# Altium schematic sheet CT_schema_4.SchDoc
size 300 x 247 mm
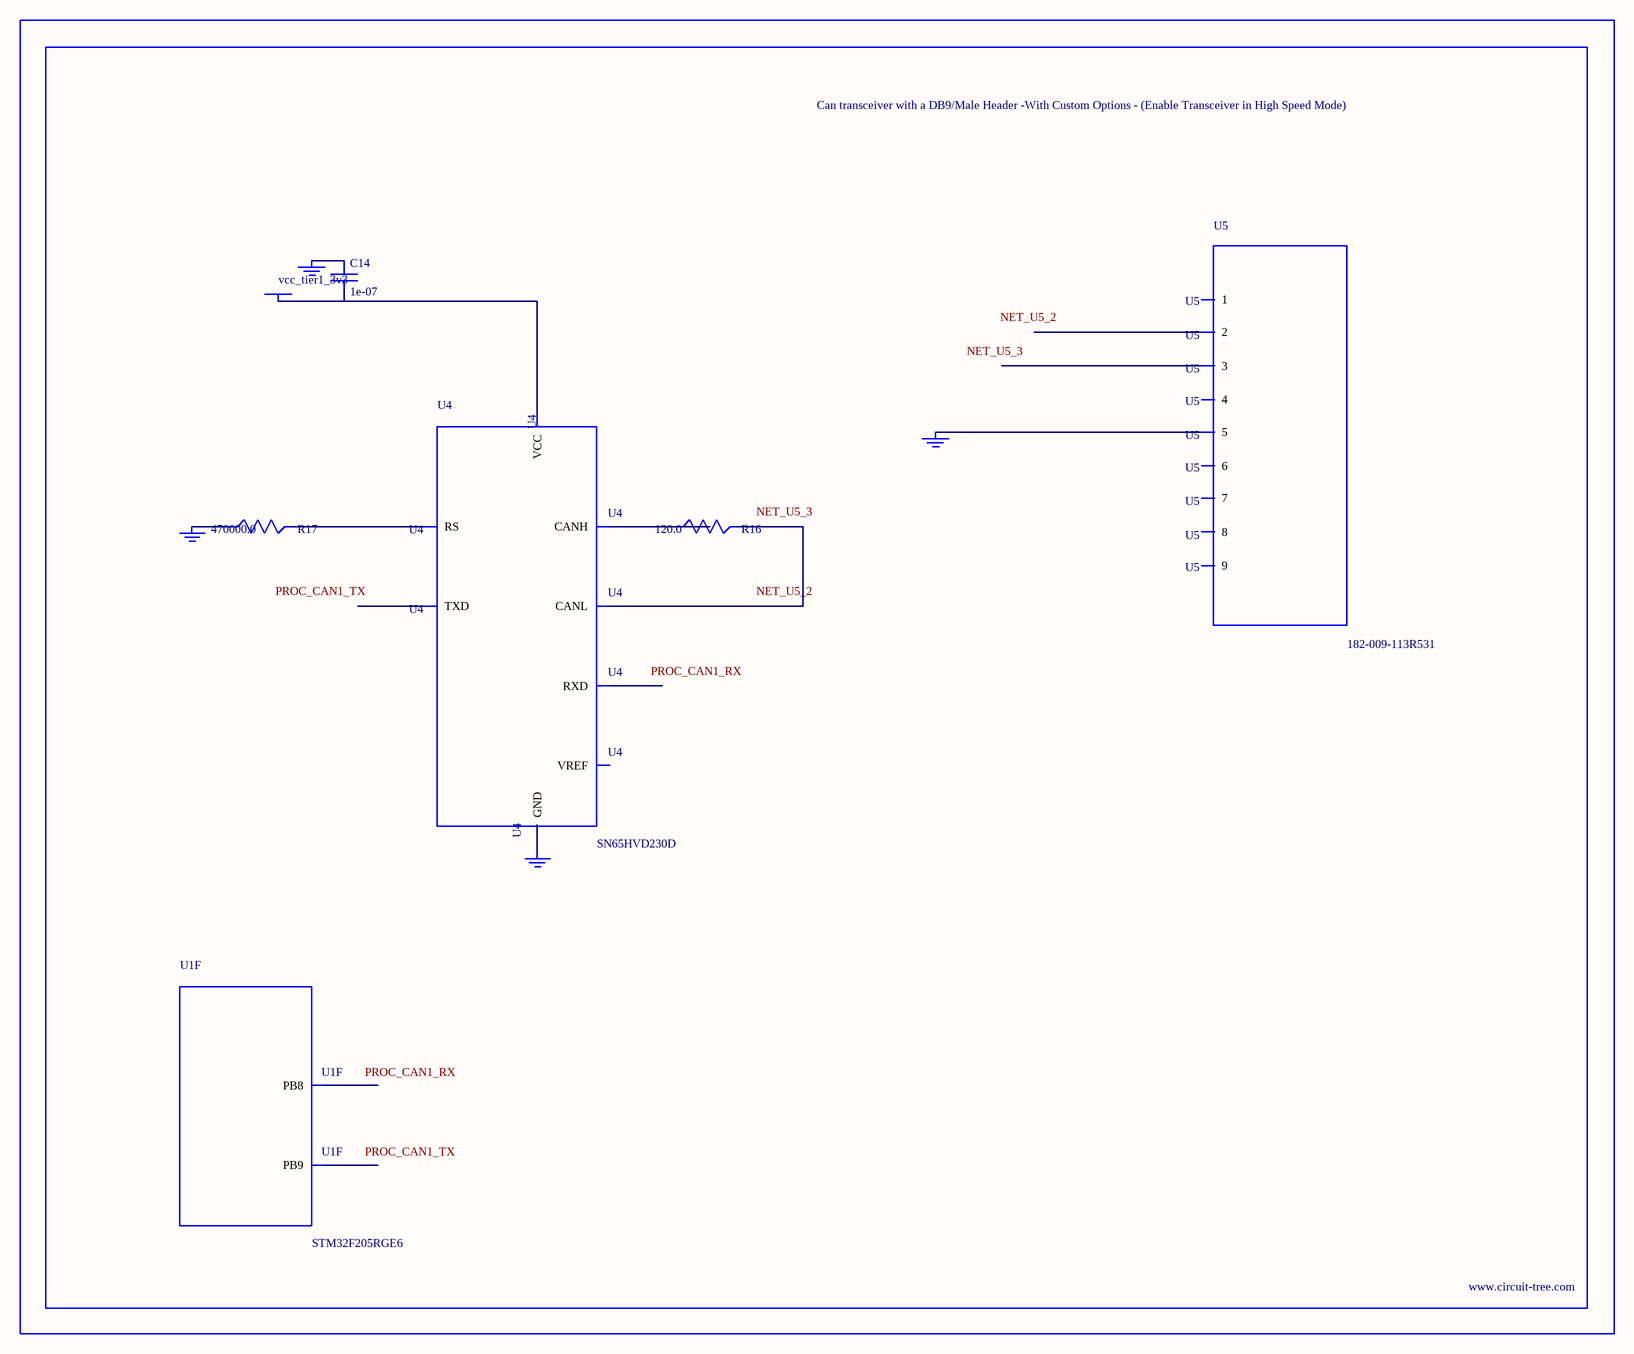
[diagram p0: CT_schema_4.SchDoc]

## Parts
BORDER3  (no value)
C14  1e-07  [C0402]
GND_INSTANCE_3_0  (no value)
GND_INSTANCE_3_1  (no value)
GND_INSTANCE_3_2  (no value)
GND_INSTANCE_3_3  (no value)
POWER_INSTANCE_3_0  vcc_tier1_3v3
R16  120.0  [R0603]
R17  470000.0  [R0603]
U1  STM32F205RGE6  [EWLCSP66]  (part F of 7)
U4  SN65HVD230D  [SOIC-8]
U5  182-009-113R531  [182-009-MALE]

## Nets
NetC14_1: C14.1 GND_INSTANCE_3_0.0(GND)
NetC14_2: C14.2 POWER_INSTANCE_3_0.0(PWR) U4.3(VCC)
NetGND_INSTANCE_3_1_0: GND_INSTANCE_3_1.0(GND) R17.1
NetGND_INSTANCE_3_2_0: GND_INSTANCE_3_2.0(GND) U4.2(GND)
NetGND_INSTANCE_3_3_0: GND_INSTANCE_3_3.0(GND) U5.5
NetR16_1: R16.1 U4.7(CANH)
NetR16_2: R16.2 U4.6(CANL)
NetR17_2: R17.2 U4.8(RS)

Not connected (* = marked no-connect by the designer): U1 A7(PB9) B7(PB8); U4 1(TXD) 4(RXD) 5(VREF); U5 1 2 3 4 6 7 8 9

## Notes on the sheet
- Labels drawn without touching a wire or pin: NET_U5_2, NET_U5_3, PROC_CAN1_RX, PROC_CAN1_TX

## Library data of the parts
BORDER3 = BORDER_PAGE3
C14 = C0402C104K3RACTU
GND_INSTANCE_3_0-GND_INSTANCE_3_3 = GND
POWER_INSTANCE_3_0 = PWR
R16 = RC0603JR-07120RL
R17 = RC0603JR-07470KL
